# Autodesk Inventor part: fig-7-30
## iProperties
Shininess: 77.0
Length Units: 11269
Angle Units: 11279
Time Units: 11290
Mass Units: 11283
Length Display Precision: 3
Angle Display Precision: 2
Created: 2002-01
Part Number: fig-7-30
Document SubType Name: Modeling
Designer: CADSoft
Density: 0.0
Volumn: 0.0
Area: 0.0
PropertySet Name: Model Information
Control State: 0
Master: False
Checked Out: False
Author: CADSoft
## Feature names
1. Extrusion2
2. Coil6
